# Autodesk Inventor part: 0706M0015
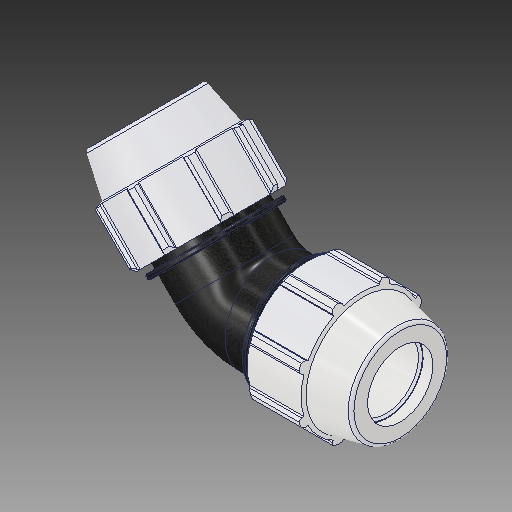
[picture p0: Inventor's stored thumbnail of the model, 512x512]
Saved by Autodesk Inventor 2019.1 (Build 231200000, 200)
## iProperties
Created: 2017-02
Part Number: 0706M0015
Material: PVC-Piping
Description: PLASSON 45° ELBOW 1 1/2'' - 1 1/2''
Document SubType Name: Modeling
Designer: KIM
Mass: 92.6774 g
Surface Area: 199.44 cm^2
Volume: 66.1981 cm^3
Density: 1.4 g/cm^3
Appearance: PTFE
Author: KIM
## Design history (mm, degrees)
derived "0706M0.ipt"
feature "Solid1::0706M0.ipt"
tag "TaggingFeature1"
body "Solid1"
other parameters: "d2" = 48.1, "d4" = 9.16517, "d5" = 27.4955, "d7" = 96.012, "d9" = 15.71171, "d11" = 3.66607, "d13" = 120 deg, "d14" = 72.15, "d15" = 12 deg, "d16" = 83.53044, "d18" = 2.405, "d19" = 35 deg, "d20" = 17.5 deg, "d21" = 89.29116, "d23" = 0, "d25" = 360 deg, "d27" = 1.92024, "d33" = 0.962, "d42" = 40.69334, "d43" = 2.88036, "d46" = 1.443, "d51" = 109.982, "d59" = 135 deg, "d63" = 92.964, "d67" = 72.009, "d68" = 3.66607, "d72" = 1.5, "d73" = 0, "d74" = 0, "d_" = 48.1, "E_" = 96.012, "A_" = 109.982, "l_" = 92.964
